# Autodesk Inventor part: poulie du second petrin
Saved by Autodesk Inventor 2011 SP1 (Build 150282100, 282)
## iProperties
Created: 2010-12
Part Number: poulie du second petrin
Document SubType Name: Modeling
Designer: eric
Density: 1 g/cm^3
Mass: 23.9527 g
Surface Area: 197.526 cm^2
Volume: 23.9527 cm^3
Author: eric
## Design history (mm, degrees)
feature "Base1"
node "Solide1"
node "Corps solides"
node "Corps surfaciques"
